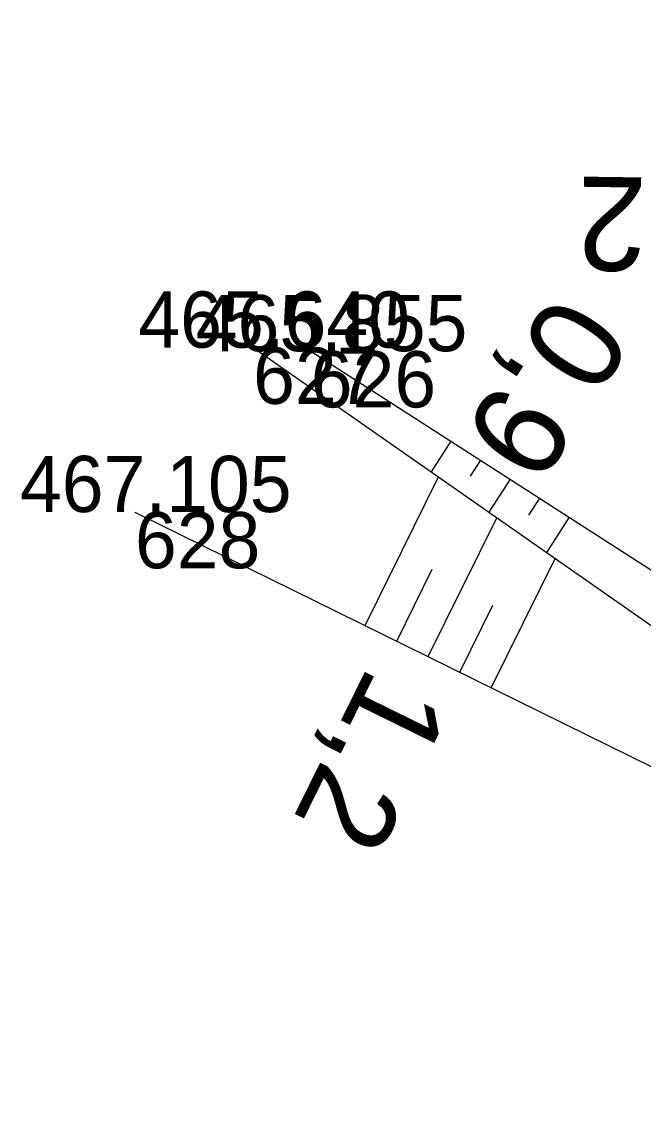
# Model space of a CAD drawing. Extents: x -1234191 to 23050, y -1290331 to -741191.
# Drawn here: x -865135.87 to -865122.59, y -1109648.88 to -1109625.72 of the extents above; entities that cross this region are included whole.
import ezdxf

# ---------------------------------------------------------------- set-up
doc = ezdxf.new("R2010")
doc.units = 0
for name, color, linetype in [('Vrstva 48', 7, 'Continuous'), ('Vrstva 49', 7, 'Continuous'), ('Vrstva 60', 7, 'Continuous'), ('Vrstva 61', 7, 'Continuous')]:
    doc.layers.add(name, color=color, linetype=linetype)

msp = doc.modelspace()

# ---------------------------------------------------------------- linework, layer by layer
at = {"layer": 'Vrstva 48'}
for p, q in [((-865126.7, -1109634.681), (-865127.121, -1109635.336)), ((-865126.069, -1109635.086), (-865126.287, -1109635.426)), ((-865128.53, -1109638.616), (-865126.967, -1109635.443)), ((-865125.438, -1109635.492), (-865125.89, -1109636.195)), ((-865124.807, -1109635.897), (-865125.041, -1109636.261)), ((-865127.184, -1109639.279), (-865125.722, -1109636.312)), ((-865124.176, -1109636.303), (-865124.659, -1109637.054)), ((-865125.839, -1109639.942), (-865124.478, -1109637.18)), ((-865127.857, -1109638.947), (-865127.101, -1109637.412)), ((-865126.511, -1109639.61), (-865125.806, -1109638.178))]:
    msp.add_line(p, q, dxfattribs=at)
at = {"layer": 'Vrstva 49'}
for points in [[(-865129.694, -1109632.757), (-865119.807, -1109639.11), (-865119.389, -1109608.332), (-865117.964, -1109586.753)], [(-865130.925, -1109632.681), (-865116.266, -1109642.911)], [(-865133.448, -1109636.192), (-865119.474, -1109643.078), (-865118.435, -1109648.881)]]:
    msp.add_lwpolyline(points, dxfattribs=at)
at = {"layer": 'Vrstva 60'}
for p, q in [((-865130.925, -1109632.681), (-865130.925, -1109632.681)), ((-865129.694, -1109632.757), (-865129.694, -1109632.757)), ((-865133.448, -1109636.192), (-865133.448, -1109636.192))]:
    msp.add_line(p, q, dxfattribs=at)

# ---------------------------------------------------------------- texts
at = {"layer": 'Vrstva 48'}
for s, rotation, p in [('1,2', 179.2219, (-865120.273, -1109629.078)), ('0,9', 237.2768, (-865124.48, -1109631.449)), ('1,2', 243.7672, (-865128.45, -1109639.423))]:
    msp.add_text(s, height=2, rotation=rotation, dxfattribs=at).set_placement(p)
at = {"layer": 'Vrstva 60'}
for s, p in [('627', (-865130.925, -1109633.881)), ('626', (-865129.694, -1109633.957)), ('628', (-865133.448, -1109637.392))]:
    msp.add_text(s, height=1.2, dxfattribs=at).set_placement(p)
at = {"layer": 'Vrstva 61'}
for s, p in [('465.640', (-865133.376, -1109632.681)), ('465.855', (-865132.15, -1109632.757)), ('467.105', (-865135.904, -1109636.192))]:
    msp.add_text(s, height=1.2, dxfattribs=at).set_placement(p)

doc.saveas('drawing.dxf')
